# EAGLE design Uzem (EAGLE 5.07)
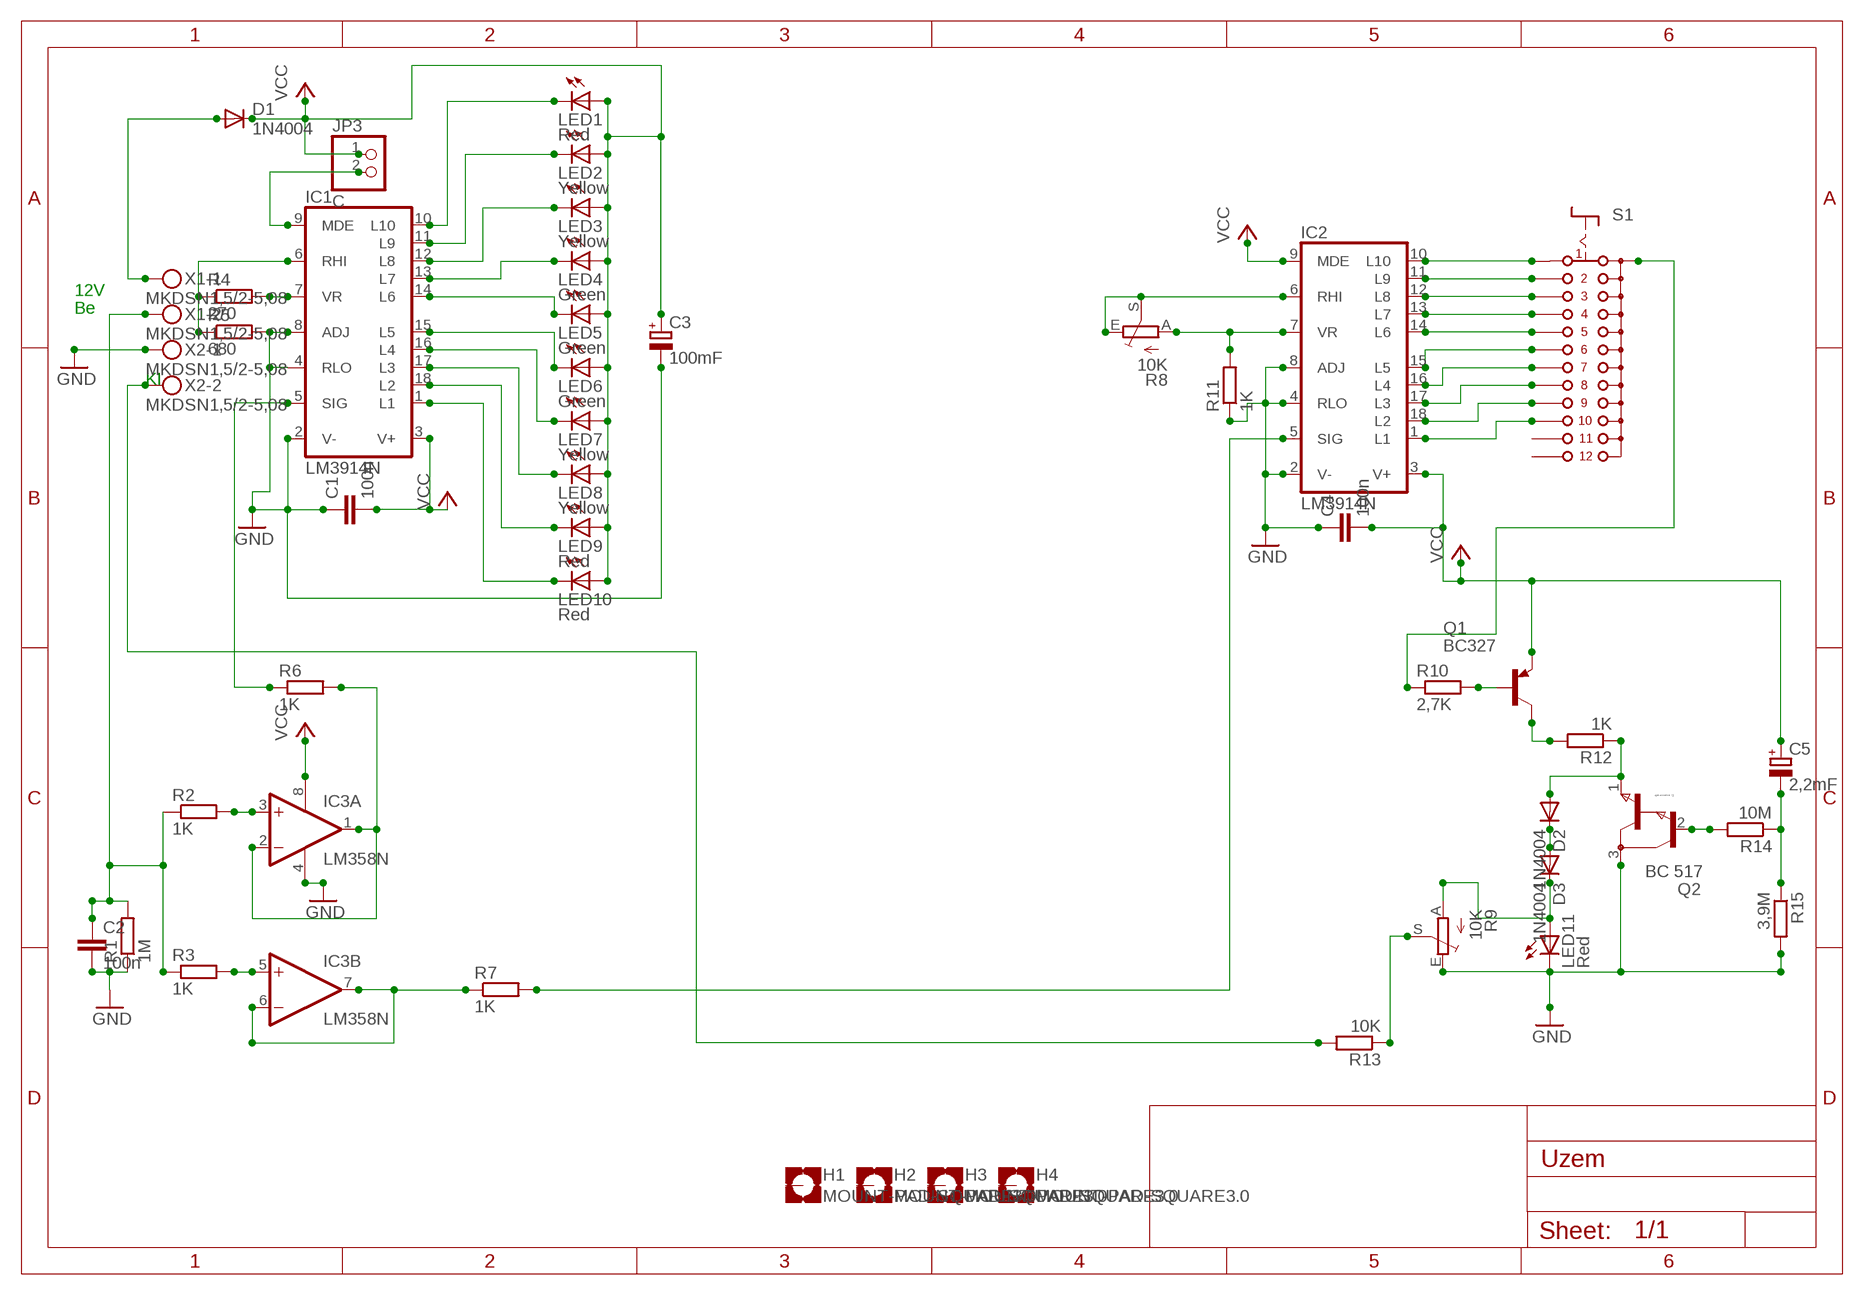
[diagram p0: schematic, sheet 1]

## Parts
C1  100n  C-EU025-025X050  [C025-025X050]
C2  100n  C-EU025-025X050  [C025-025X050]
C3  100mF  CPOL-EUE2,5-6E  [E2,5-6E]
C4  100n  C-EU025-025X050  [C025-025X050]
C5  2,2mF  CPOL-EUE2,5-6E  [E2,5-6E]
D1  1N4004  [DO41-10]
D2  1N4004  [DO41-10]
D3  1N4004  [DO41-10]
H1  MOUNT-PAD-SQUARE3.0  [3,0-PAD-SQUARE]
H2  MOUNT-PAD-SQUARE3.0  [3,0-PAD-SQUARE]
H3  MOUNT-PAD-SQUARE3.0  [3,0-PAD-SQUARE]
H4  MOUNT-PAD-SQUARE3.0  [3,0-PAD-SQUARE]
IC1  LM3914N  [DIL18]
IC2  LM3914N  [DIL18]
IC3  LM358N  [DIL08]
JP3  C  PINHD-1X2  [1X02]
LED1  Red  LED5MM  [LED5MM]
LED2  Yellow  LED5MM  [LED5MM]
LED3  Yellow  LED5MM  [LED5MM]
LED4  Green  LED5MM  [LED5MM]
LED5  Green  LED5MM  [LED5MM]
LED6  Green  LED5MM  [LED5MM]
LED7  Yellow  LED5MM  [LED5MM]
LED8  Yellow  LED5MM  [LED5MM]
LED9  Red  LED5MM  [LED5MM]
LED10  Red  LED5MM  [LED5MM]
LED11  Red  LED5MM  [LED5MM]
Q1  BC327  [TO92]
Q2  BC 517  BC517  [TO92]
R1  1M  R-EU_0204/7  [0204/7]
R2  1K  R-EU_0204/7  [0204/7]
R3  1K  R-EU_0204/7  [0204/7]
R4  270  R-EU_0204/7  [0204/7]
R5  680  R-EU_0204/7  [0204/7]
R6  1K  R-EU_0204/7  [0204/7]
R7  1K  R-EU_0204/7  [0204/7]
R8  10K  TRIM_EU-CA6V  [CA6V]
R9  10K  TRIM_EU-CA6V  [CA6V]
R10  2,7K  R-EU_0204/7  [0204/7]
R11  1K  R-EU_0204/7  [0204/7]
R12  1K  R-EU_0204/7  [0204/7]
R13  10K  R-EU_0204/7  [0204/7]
R14  10M  R-EU_0204/7  [0204/7]
R15  3,9M  R-EU_0204/7  [0204/7]
S1  CK101X12  [CK101X12]
X1  MKDSN1,5/2-5,08  [MKDSN1,5/2-5,08]
X2  MKDSN1,5/2-5,08  [MKDSN1,5/2-5,08]

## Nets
GND: C1.1 C2.2 C3.- C4.1 IC1.2(V-) IC1.4(RLO) IC1.8(ADJ) IC2.2(V-) IC2.4(RLO) IC2.8(ADJ) IC3.4(P:V-) LED11.K(C) Q2.3(C) R1.1 R5.2 R9.E R11.1 R15.2 X2.1
N$1: IC1.10(L10) LED1.K(C)
N$2: IC1.5(SIG) R6.1
N$3: IC1.11(L9) LED2.K(C)
N$4: IC1.12(L8) LED3.K(C)
N$5: IC1.13(L7) LED4.K(C)
N$6: IC1.14(L6) LED5.K(C)
N$7: IC1.15(L5) LED6.K(C)
N$8: IC1.16(L4) LED7.K(C)
N$9: IC1.17(L3) LED8.K(C)
N$10: IC1.18(L2) LED9.K(C)
N$11: IC1.1(L1) LED10.K(C)
N$12: IC2.5(SIG) R7.2
N$13: C2.1 R1.2 R2.1 R3.1 X1.2
N$15: IC1.6(RHI) R4.1 R5.1
N$16: IC3.3(A:+IN) R2.2
N$17: IC3.5(B:+IN) R3.2
N$18: IC1.7(VR) R4.2
N$19: IC2.15(L5) S1.6
N$20: IC2.14(L6) S1.5
N$21: Q1.2(B) R10.2
N$23: IC2.13(L7) S1.4
N$24: IC2.12(L8) S1.3
N$25: IC2.11(L9) S1.2
N$26: IC2.10(L10) S1.1
N$27: R10.1 S1.A
N$28: IC2.18(L2) S1.9
N$29: IC2.1(L1) S1.10
N$30: IC3.1(A:OUT) IC3.2(A:-IN) R6.2
N$31: D2.C D3.A
N$32: IC3.6(B:-IN) IC3.7(B:OUT) R7.1
N$33: D3.C LED11.A R9.A
N$34: Q1.3(C) R12.2
N$35: D2.A Q2.1(E) R12.1
N$36: R9.S R13.1
N$37: Q2.2(B) R14.2
N$38: IC2.7(VR) R8.A R11.2
N$39: R13.2 X2.2
N$40: IC1.9(MDE) JP3.2
N$43: C5.- R14.1 R15.1
N$44: IC2.6(RHI) R8.E R8.S
N$45: D1.A X1.1
N$51: IC2.16(L4) S1.7
N$52: IC2.17(L3) S1.8
VCC: C1.2 C3.+ C4.2 C5.+ D1.C IC1.3(V+) IC2.3(V+) IC2.9(MDE) IC3.8(P:V+) JP3.1 LED1.A LED2.A LED3.A LED4.A LED5.A LED6.A LED7.A LED8.A LED9.A LED10.A Q1.1(E)
Unconnected: H1.B3,0(MOUNT) H2.B3,0(MOUNT) H3.B3,0(MOUNT) H4.B3,0(MOUNT) S1.11 S1.12

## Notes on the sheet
- 12V
- Be
- KI

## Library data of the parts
C1 C2 C4 = rcl:C-EU: CAPACITOR, European symbol
C3 C5 = rcl:CPOL-EU: POLARIZED CAPACITOR, European symbol
D1-D3 = diode-1:1N4004: DIODE
H1-H4 = holes:MOUNT-PAD-SQUARE: MOUNTING PAD, square
IC1 IC2 = linear4:LM3914N: LED DRIVER senses analog voltage levels and drives 10 LEDs
IC3 = linear4:LM358: OP AMP
JP3 = pinhead:PINHD-1X2: PIN HEADER
LED1-LED11 = led:LED: LED
Q1 = transistor-pnp:BC327: PNP Transistor
Q2 = NPN:BC517
R1-R7 R10-R15 = rcl:R-EU_: RESISTOR, European symbol
R8 R9 = pot:TRIM_EU-: POTENTIOMETER
S1 = switch:CK101X12: ROTARY SWITCH C&K
X1 X2 = con-phoenix-508:MKDSN1,5/2-5,08: MKDSN 1,5/ 2-5,08 Printklemme

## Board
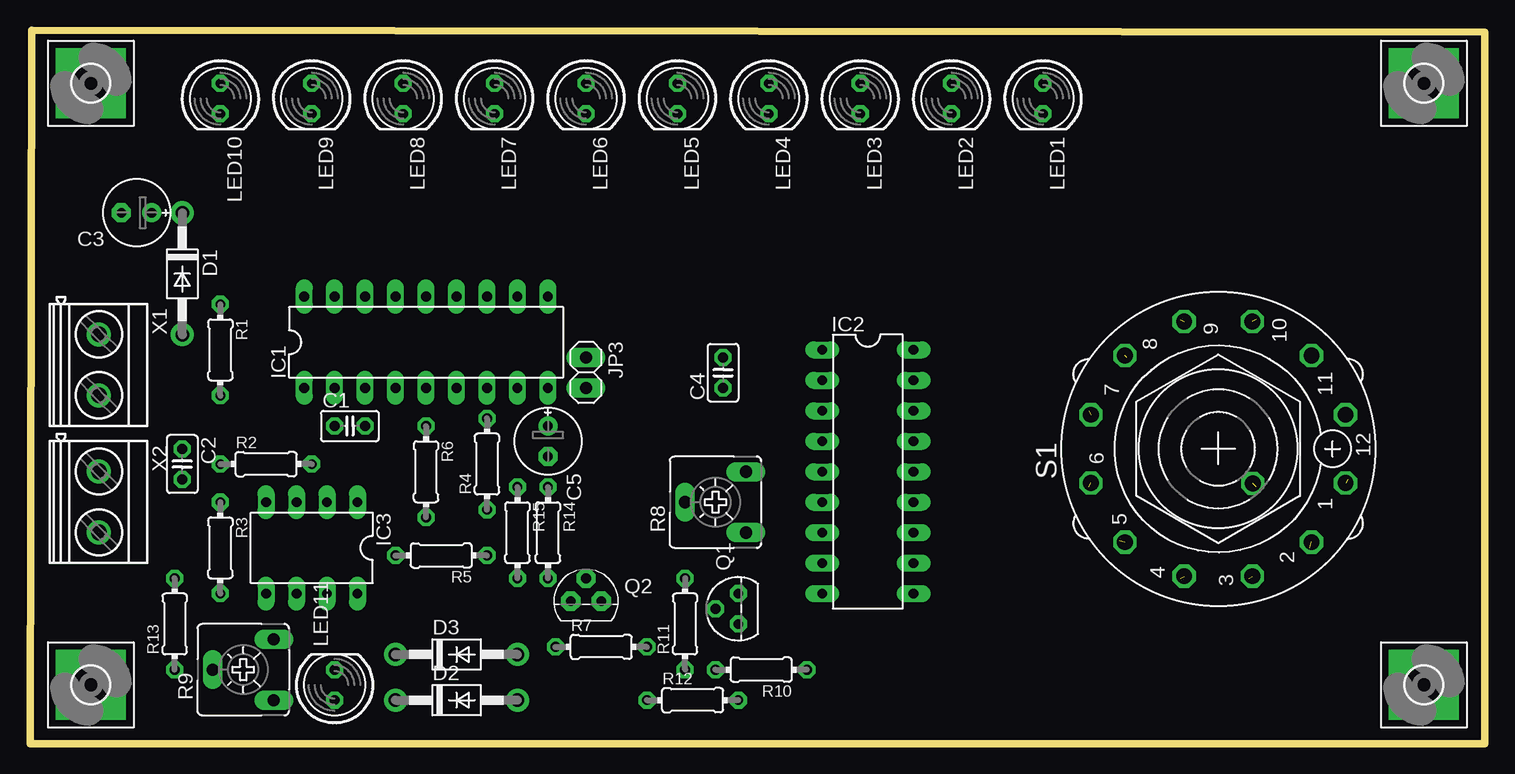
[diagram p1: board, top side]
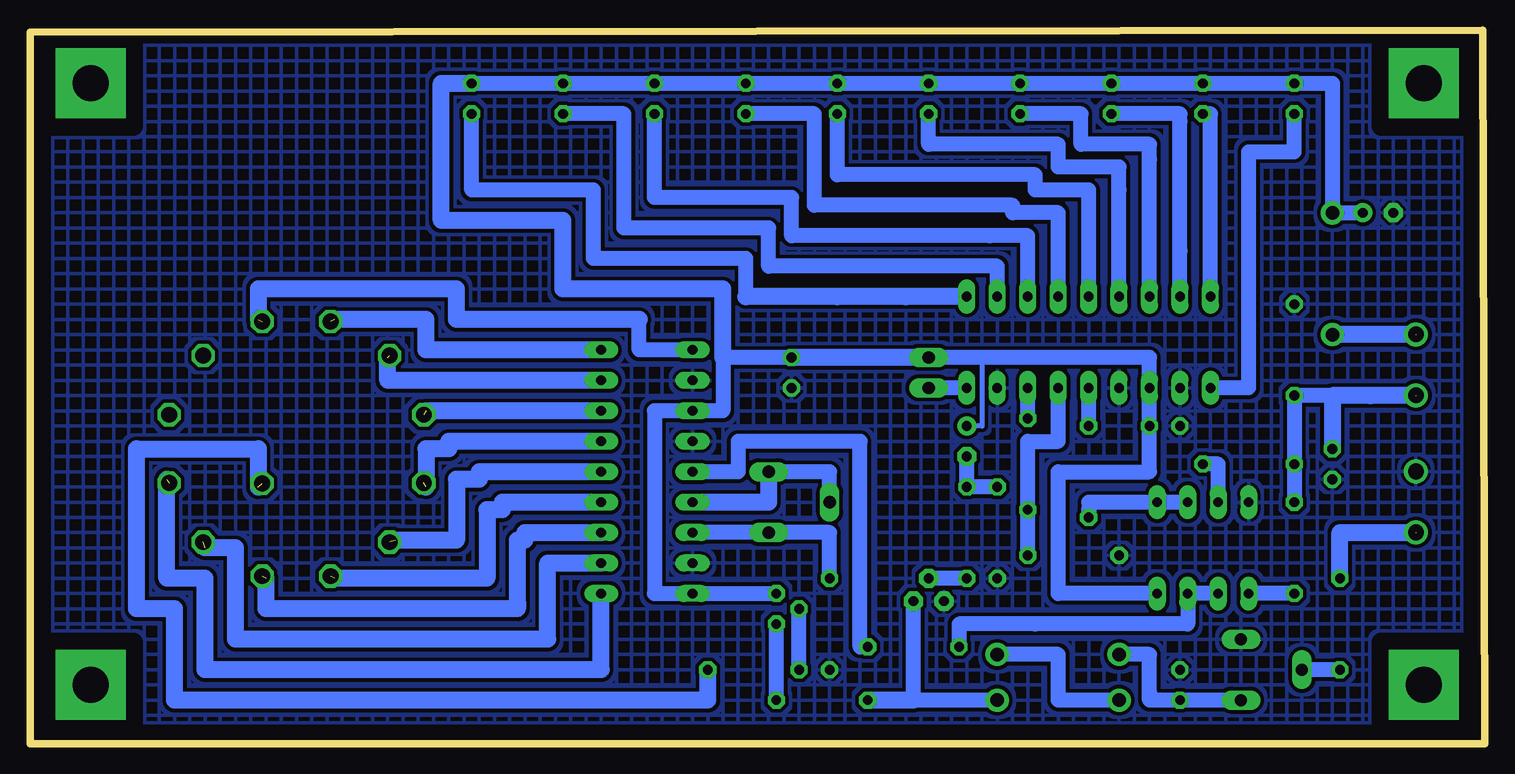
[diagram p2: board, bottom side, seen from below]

Size 121.27 x 59.53 mm. Coordinates in mm from the lower left corner, seen from the top.
Outline: 0,0 121.27,0 121.27,59.36 0.16,59.53 0,0
Copper layers (1*16): Top 0.035mm / dielectric 1.5mm / Bottom 0.035mm
Design rules "Dino": minimum track width 12mil, minimum drill 0.8mm, track to track 12mil, track to pad 12mil, pad to pad 12mil, via to via 12mil, smd to smd 8mil, copper to edge 12mil, drill to drill 16mil, minimum pad ring 12mil, minimum via ring 12mil, stop-mask expansion 4mil, vias tented up to drill 0mil, thermal gap 10mil

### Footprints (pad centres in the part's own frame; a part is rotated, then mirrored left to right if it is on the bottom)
C025-025X050 = drill 0.813 octagon: 1 -1.27,0; 2 1.27,0
E2,5-6E = drill 0.813 pad 1.575 round: + -1.27,0 | drill 0.813 pad 1.575 octagon: - 1.27,0
DO41-10 = drill 1.118 pad 1.93 round: A 5.08,0; C -5.08,0
3,0-PAD-SQUARE = drill 3 pad 5.842 square: B3,0 0,0
DIL18 = drill 0.813 long: 1 -10.16,-3.81; 2 -7.62,-3.81; 3 -5.08,-3.81; 4 -2.54,-3.81; 5 0,-3.81; 6 2.54,-3.81; 7 5.08,-3.81; 8 7.62,-3.81; 9 10.16,-3.81; 10 10.16,3.81; 11 7.62,3.81; 12 5.08,3.81; 13 2.54,3.81; 14 0,3.81; 15 -2.54,3.81; 16 -5.08,3.81; 17 -7.62,3.81; 18 -10.16,3.81
DIL08 = drill 0.813 long: 1 -3.81,-3.81; 2 -1.27,-3.81; 3 1.27,-3.81; 4 3.81,-3.81; 5 3.81,3.81; 6 1.27,3.81; 7 -1.27,3.81; 8 -3.81,3.81
1X02 = drill 1.016 long: 1 -1.27,0; 2 1.27,0
LED5MM = drill 0.813 octagon: A -1.27,0; K 1.27,0
TO92 = drill 0.813 octagon: 1 1.27,0; 2 0,1.905; 3 -1.27,0
TO92' = drill 0.813 pad 1.6 octagon: 1 1.27,0; 2 0,1.905; 3 -1.27,0
0204/7 = drill 0.813 octagon: 1 -3.81,0; 2 3.81,0
CA6V = drill 1.016 long: A -2.54,-2.54; E 2.54,-2.54; S 0,2.54
CK101X12 = drill 1.321 octagon: 1 -2.845,-10.617; 2 -7.772,-7.772; 3 -10.617,-2.845; 4 -10.617,2.845; 5 -7.772,7.772; 6 -2.845,10.617; 7 2.845,10.617; 8 7.772,7.772; 9 10.617,2.845; 10 10.617,-2.845; 11 7.772,-7.772; 12 2.845,-10.617; A -2.87,-2.87
MKDSN1,5/2-5,08 = drill 1.3 pad 2 round: 1 -2.561,0.025; 2 2.519,0.025

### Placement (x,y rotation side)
C1  26.67,26.51 0 top
C2  12.69,23.33 270 top
C3  8.88,44.29 180 top
C4  57.78,30.95 90 top
C5  43.17,25.23 270 top
D1  12.69,39.2 270 top
D2  35.55,3.65 0 top
D3  35.55,7.46 0 top
H1  5.08,55.08 0 top
H2  5.08,4.92 0 top
H3  116.2,4.92 0 top
H4  116.2,55.08 0 top
IC1  33.02,33.49 0 top
IC2  69.84,22.7 270 top
IC3  23.49,16.35 180 top
JP3  46.35,30.95 270 top
LED1  84.45,53.81 270 top
LED2  76.83,53.81 270 top
LED3  69.21,53.81 270 top
LED4  61.59,53.81 270 top
LED5  53.97,53.81 270 top
LED6  46.35,53.81 270 top
LED7  38.73,53.81 270 top
LED8  31.11,53.81 270 top
LED9  23.49,53.81 270 top
LED10  15.87,53.81 270 top
LED11  25.39,4.92 90 top
Q1  59.05,11.27 90 top
Q2  BC 517  [TO92']  46.35,11.9 0 top
R1  15.87,32.86 270 top
R2  19.68,23.33 0 top
R3  15.87,16.35 270 top
R4  38.09,23.33 90 top
R5  34.28,15.71 180 top
R6  33.02,22.7 270 top
R7  47.62,8.09 0 top
R8  57.14,20.16 90 top
R9  17.78,6.18 90 top
R10  60.95,6.18 180 top
R11  54.6,10 90 top
R12  55.24,3.65 0 top
R13  12.06,10 90 top
R14  43.17,17.62 270 top
R15  40.63,17.62 270 top
S1  99.06,24.6 90 top
X1  5.71,31.59 270 top
X2  5.71,20.16 270 top

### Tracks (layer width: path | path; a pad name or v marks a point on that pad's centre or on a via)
GND
  pour Bottom (isolate 0.305, hatched): 1.9,58.26 119.38,58.26 119.38,1.74 1.9,1.74
N$1
  Bottom 1.27: 61.59,37.3 61.59,40.48 74.29,40.48 74.29,46.19 84.45,46.19 LED1.K
  Bottom 1.422: IC1.10 48.25,37.3 53.97,37.3 61.59,37.3
N$2
  Bottom 1.27: R6.1 IC1.5
N$3
  Bottom 1.27: IC1.11 40.63,39.84 59.68,39.84 59.68,43.02 71.75,43.02 71.75,52.54 LED2.K
N$4
  Bottom 1.27: IC1.12 38.09,39.2 38.09,42.38 41.27,42.38 57.78,42.38 57.78,45.55 69.21,45.55 LED3.K
N$5
  Bottom 1.27: IC1.13 35.55,40.48 35.55,44.29 39.36,44.29 39.36,44.92 55.88,44.92 55.88,52.54 LED4.K
N$6
  Bottom 1.27: IC1.14 33.02,41.74 33.02,42.38 33.02,46.19 37.46,46.19 37.46,47.46 53.97,47.46 LED5.K
N$7
  Bottom 1.27: IC1.15 30.48,46.19 30.48,48.09 35.55,48.09 35.55,50 46.35,50 LED6.K
N$8
  Bottom 1.27: IC1.16 27.94,48.73 27.94,50 33.65,50 33.65,52.54 LED7.K
N$9
  Bottom 1.27: LED8.K 25.39,52.54 25.39,51.91 25.39,41.11 IC1.17
N$10
  Bottom 1.27: IC1.18 22.86,52.54 LED9.K
N$11
  Bottom 1.27: IC1.1 19.68,29.68 19.68,49.37 15.87,49.37 LED10.K
N$12
  Bottom 1.27: IC2.5 62.22,22.7 62.22,25.23 52.06,25.23 52.06,8.09 R7.2
N$13  (1 unrouted)
  Bottom 1.27: R3.1 R2.1 R1.2 12.69,29.05 C2.1
  Bottom 1.422: C2.1 12.69,29.05 9.52,29.05 5.71,29.05
N$15
  Bottom 1.27: R5.1 R4.1 38.09,25.23 35.55,25.23 IC1.6
N$16
  Bottom 1.27: IC3.3 22.22,23.33 R2.2
N$17
  Bottom 1.27: R3.2 IC3.5
N$18
  Bottom 1.27: R4.2 IC1.7
N$19  (1 unrouted)
  Bottom 1.422: 88.26,21.43 88.26,24.6 86.36,24.6 86.36,25.23 IC2.15
N$20  (1 unrouted)
  Bottom 1.422: 90.8,16.98 85.72,16.98 85.72,22.06 83.81,22.06 83.81,22.7 IC2.14
N$21
  Bottom 1.27: R10.2 Q1.2
N$23  (1 unrouted)
  Bottom 1.422: 95.88,13.81 83.18,13.81 83.18,19.52 81.91,19.52 81.91,20.16 IC2.13
N$24  (1 unrouted)
  Bottom 1.422: 101.59,13.81 101.59,11.27 80.64,11.27 80.64,11.9 80.64,16.98 80.01,16.98 80.01,17.62 IC2.12
N$25  (1 unrouted)
  Bottom 1.422: 106.68,16.35 104.77,16.35 104.14,16.35 104.14,8.73 78.1,8.73 78.1,15.08 74.29,15.08 IC2.11
N$26  (1 unrouted)
  Bottom 1.422: 109.85,22.06 109.85,13.81 106.68,13.81 106.68,6.82 106.68,6.18 73.66,6.18 IC2.10
N$27  (1 unrouted)
  Bottom 1.422: 102.23,21.43 102.23,24.6 112.39,24.6 112.39,11.27 109.22,11.27 109.22,3.65 64.77,3.65 R10.1
N$28  (1 unrouted)
  Bottom 1.422: IC2.18 88.26,32.86 88.26,33.49 88.26,35.4 95.88,35.4
N$29  (1 unrouted)
  Bottom 1.27: IC2.1 70.48,32.86 70.48,35.4
  Bottom 1.422: 70.48,35.4 85.09,35.4 85.72,35.4 85.72,37.94 102.23,37.94 102.23,35.4
N$30
  Bottom 1.27: IC3.2 IC3.1 33.02,20.16 33.02,19.52 R6.2
N$31
  Bottom 1.27: D3.A 35.55,7.46 35.55,4.28 35.55,3.65 D2.C
N$32
  Bottom 1.27: IC3.6 IC3.7 24.76,10 37.46,10 43.81,10 R7.1
N$33
  Bottom 1.27: D3.C 27.94,7.46 27.94,4.28 27.94,3.65 LED11.A R9.A
N$34
  Bottom 1.27: R12.2 Q1.3
N$35
  Bottom 1.27: D2.A 47.62,3.65 Q2.1
  Bottom 1.422: 47.62,3.65 R12.1
N$36
  Bottom 1.27: R13.1 R9.S
N$37
  Bottom 1.27: R14.2 Q2.2
N$38
  Bottom 1.27: IC2.7 R8.A 54.6,17.62 R11.2
N$39  (1 unrouted)
  Bottom 1.422: 5.71,17.62 12.06,17.62 R13.2
N$40
  Bottom 1.27: IC1.9 JP3.2
N$41
  pour Bottom (isolate 0.305): -0.01,59.52 0.63,59.52
N$43
  Bottom 1.27: R14.1 R15.1 R14.1 | R14.1 C5.- | R14.1 C5.- | R14.1 C5.-
N$44
  Bottom 1.27: R8.E 54.6,22.7 R8.S
  Bottom 1.422: R8.E 59.68,20.16 IC2.6
N$45  (1 unrouted)
  Bottom 1.422: 5.71,34.12 D1.A
N$51  (1 unrouted)
  Bottom 1.422: IC2.16 88.26,27.78
N$52  (1 unrouted)
  Bottom 1.422: IC2.17 91.44,30.32 91.44,32.22
VCC
  Bottom 0.406: 41.9,32.22 41.9,26.51 C5.+
  Bottom 1.27: C4.2 63.49,32.22 63.49,27.78 IC2.3 69.21,27.78 69.21,12.54 IC2.9 Q1.1 | LED1.A LED2.A LED3.A LED4.A LED5.A LED6.A LED7.A LED8.A LED9.A LED10.A 12.69,55.08 12.69,46.83 D1.C C3.+ | JP3.1 41.9,32.22 27.94,32.22 IC1.3 C1.2 27.94,22.7 35.55,22.7 35.55,12.54 IC3.8
  Bottom 1.422: JP3.1 C4.2 | LED1.A 86.99,55.08 86.99,43.65 76.83,43.65 76.83,43.02 76.83,37.94 70.48,37.94 64.13,37.94 63.49,37.94 63.49,32.22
